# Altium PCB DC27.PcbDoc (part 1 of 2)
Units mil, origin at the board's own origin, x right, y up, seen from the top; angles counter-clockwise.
Board outline 2165.35 x 2165.35 mil, 4 copper layers (Top, Mid-Layer 1, Mid-Layer 2, Bottom), stack 65.59 mil thick; 50 components, 49 nets, 297 pads, 156 vias.
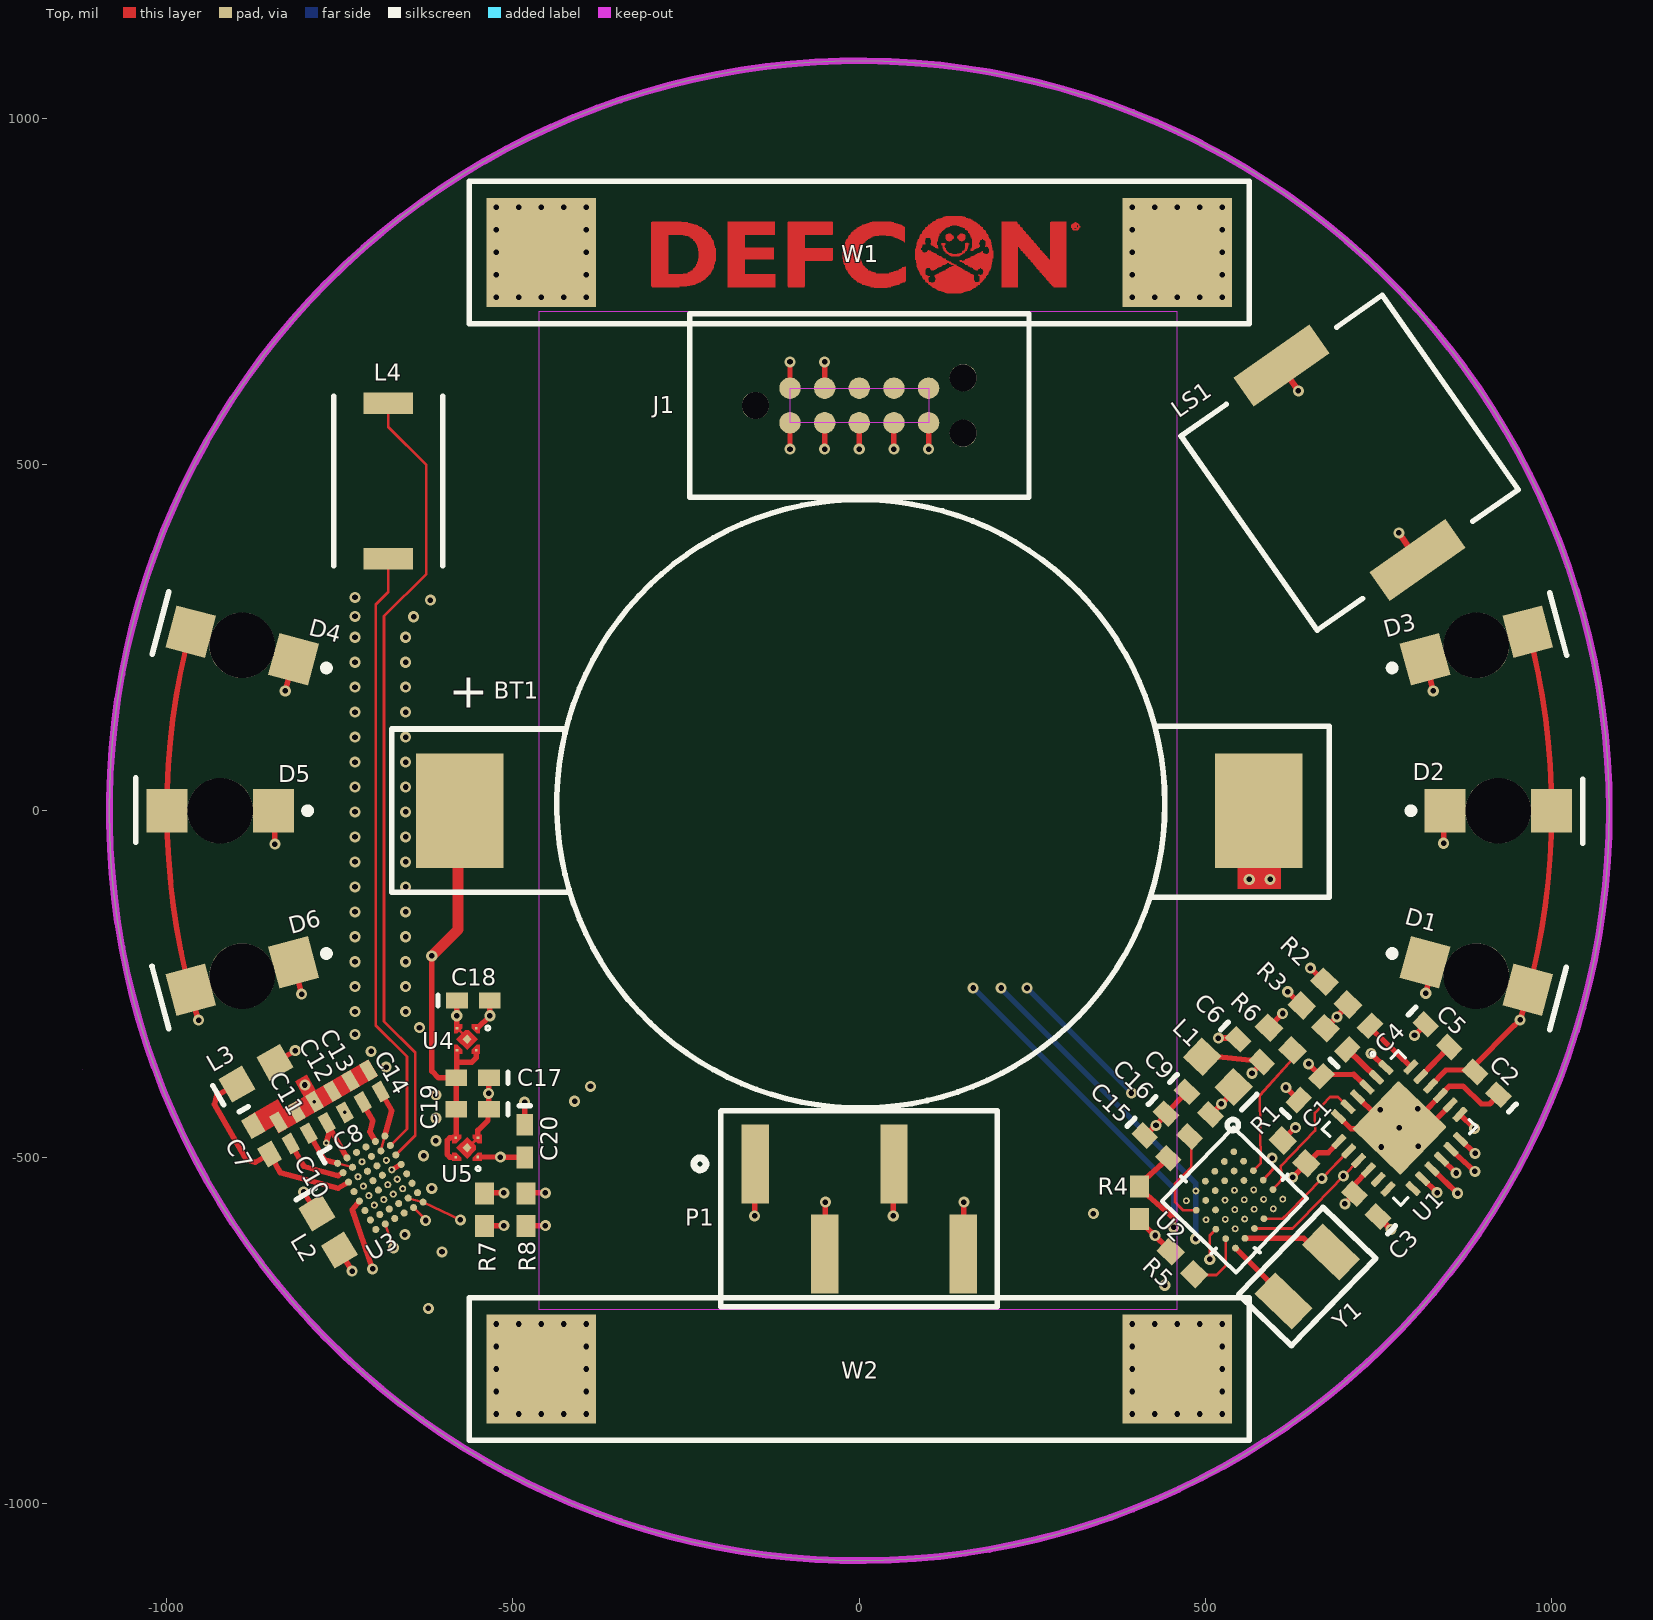
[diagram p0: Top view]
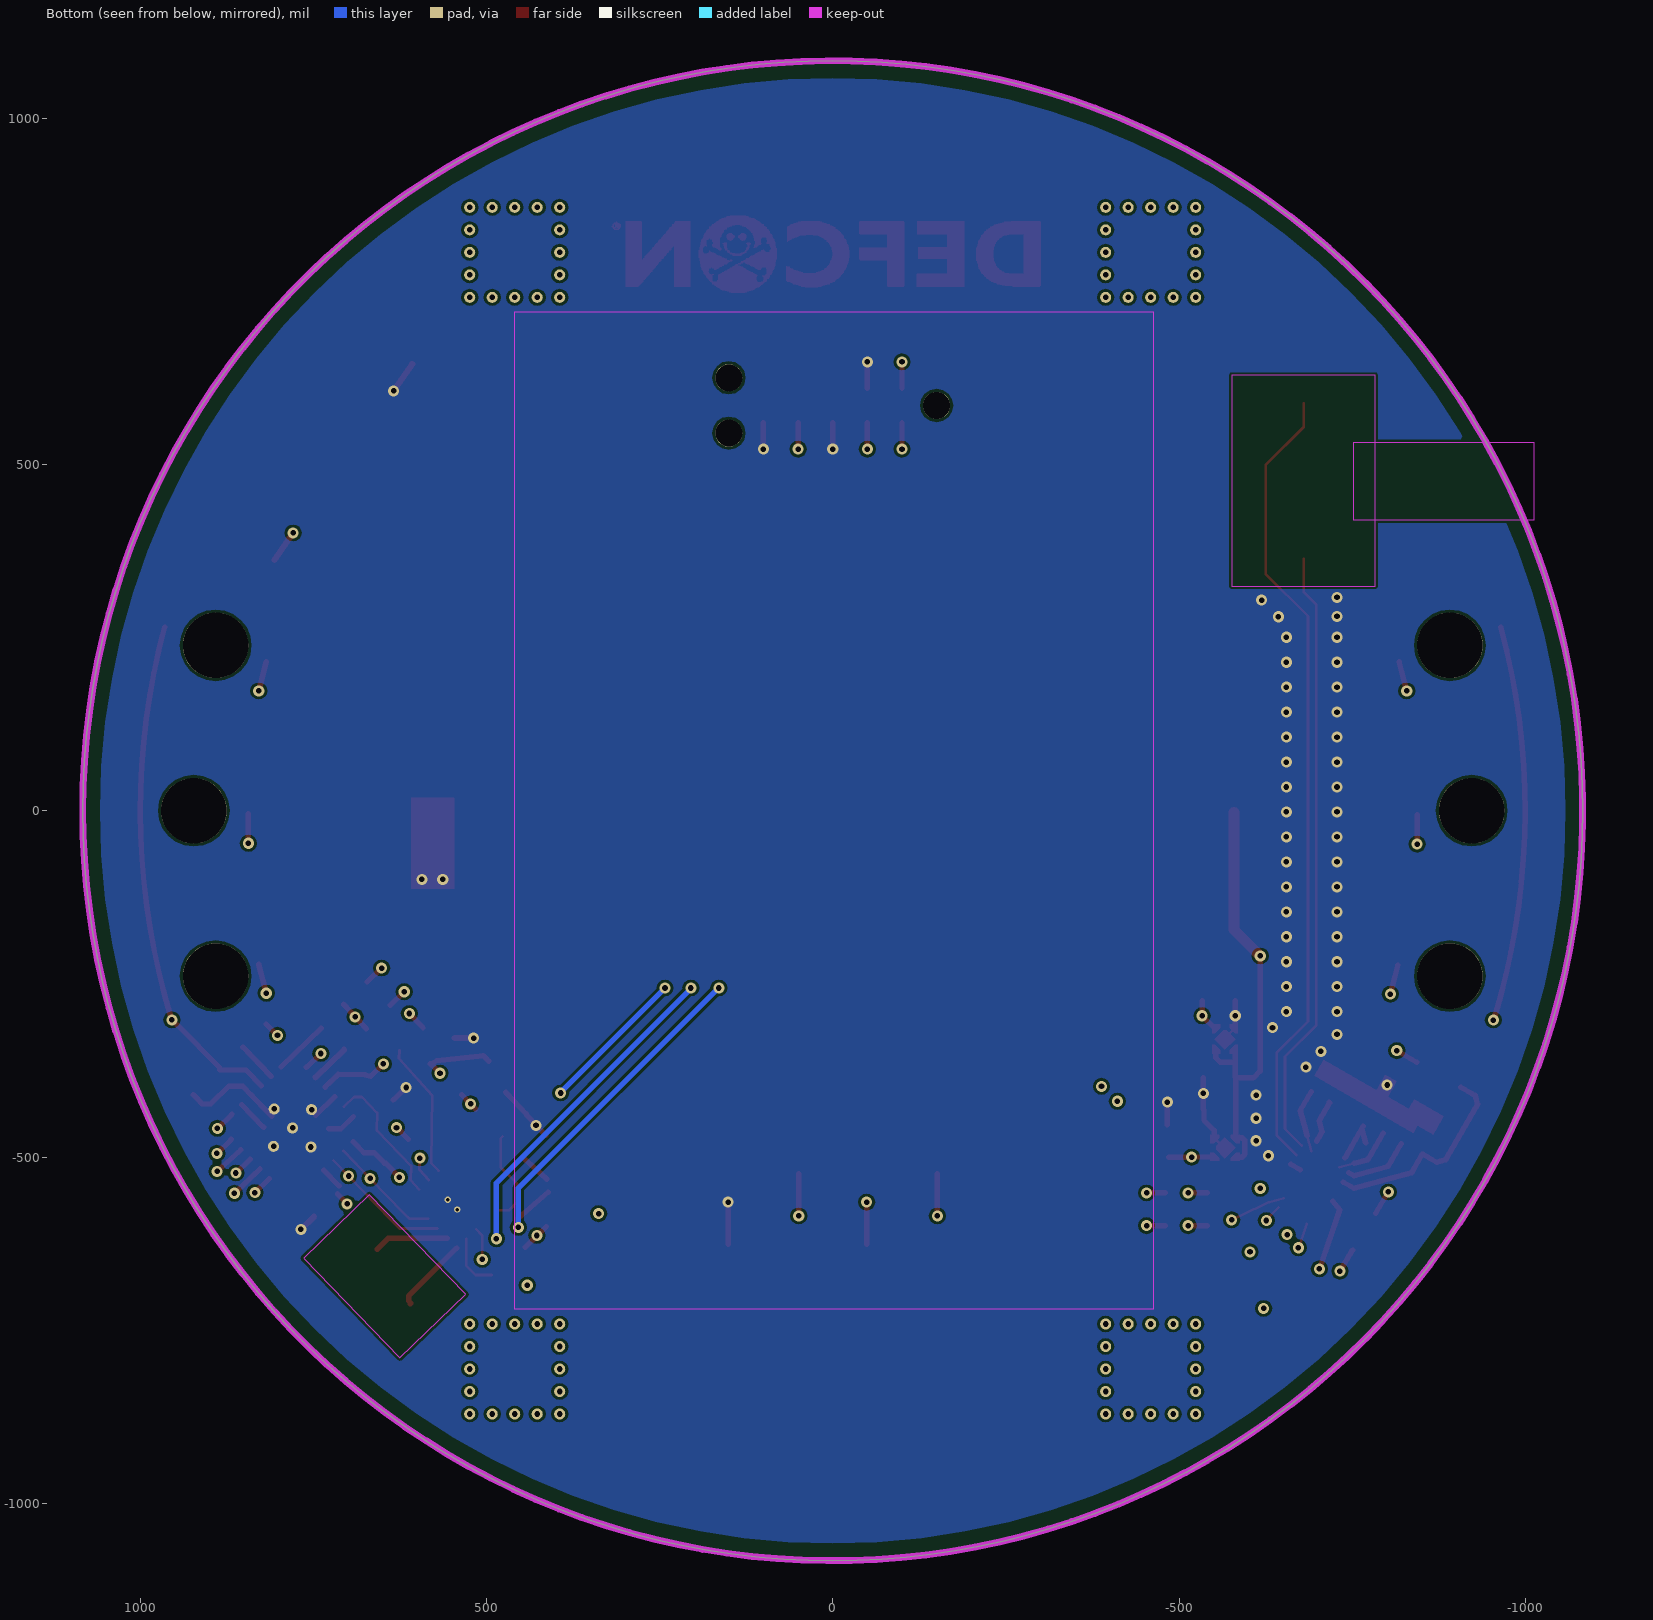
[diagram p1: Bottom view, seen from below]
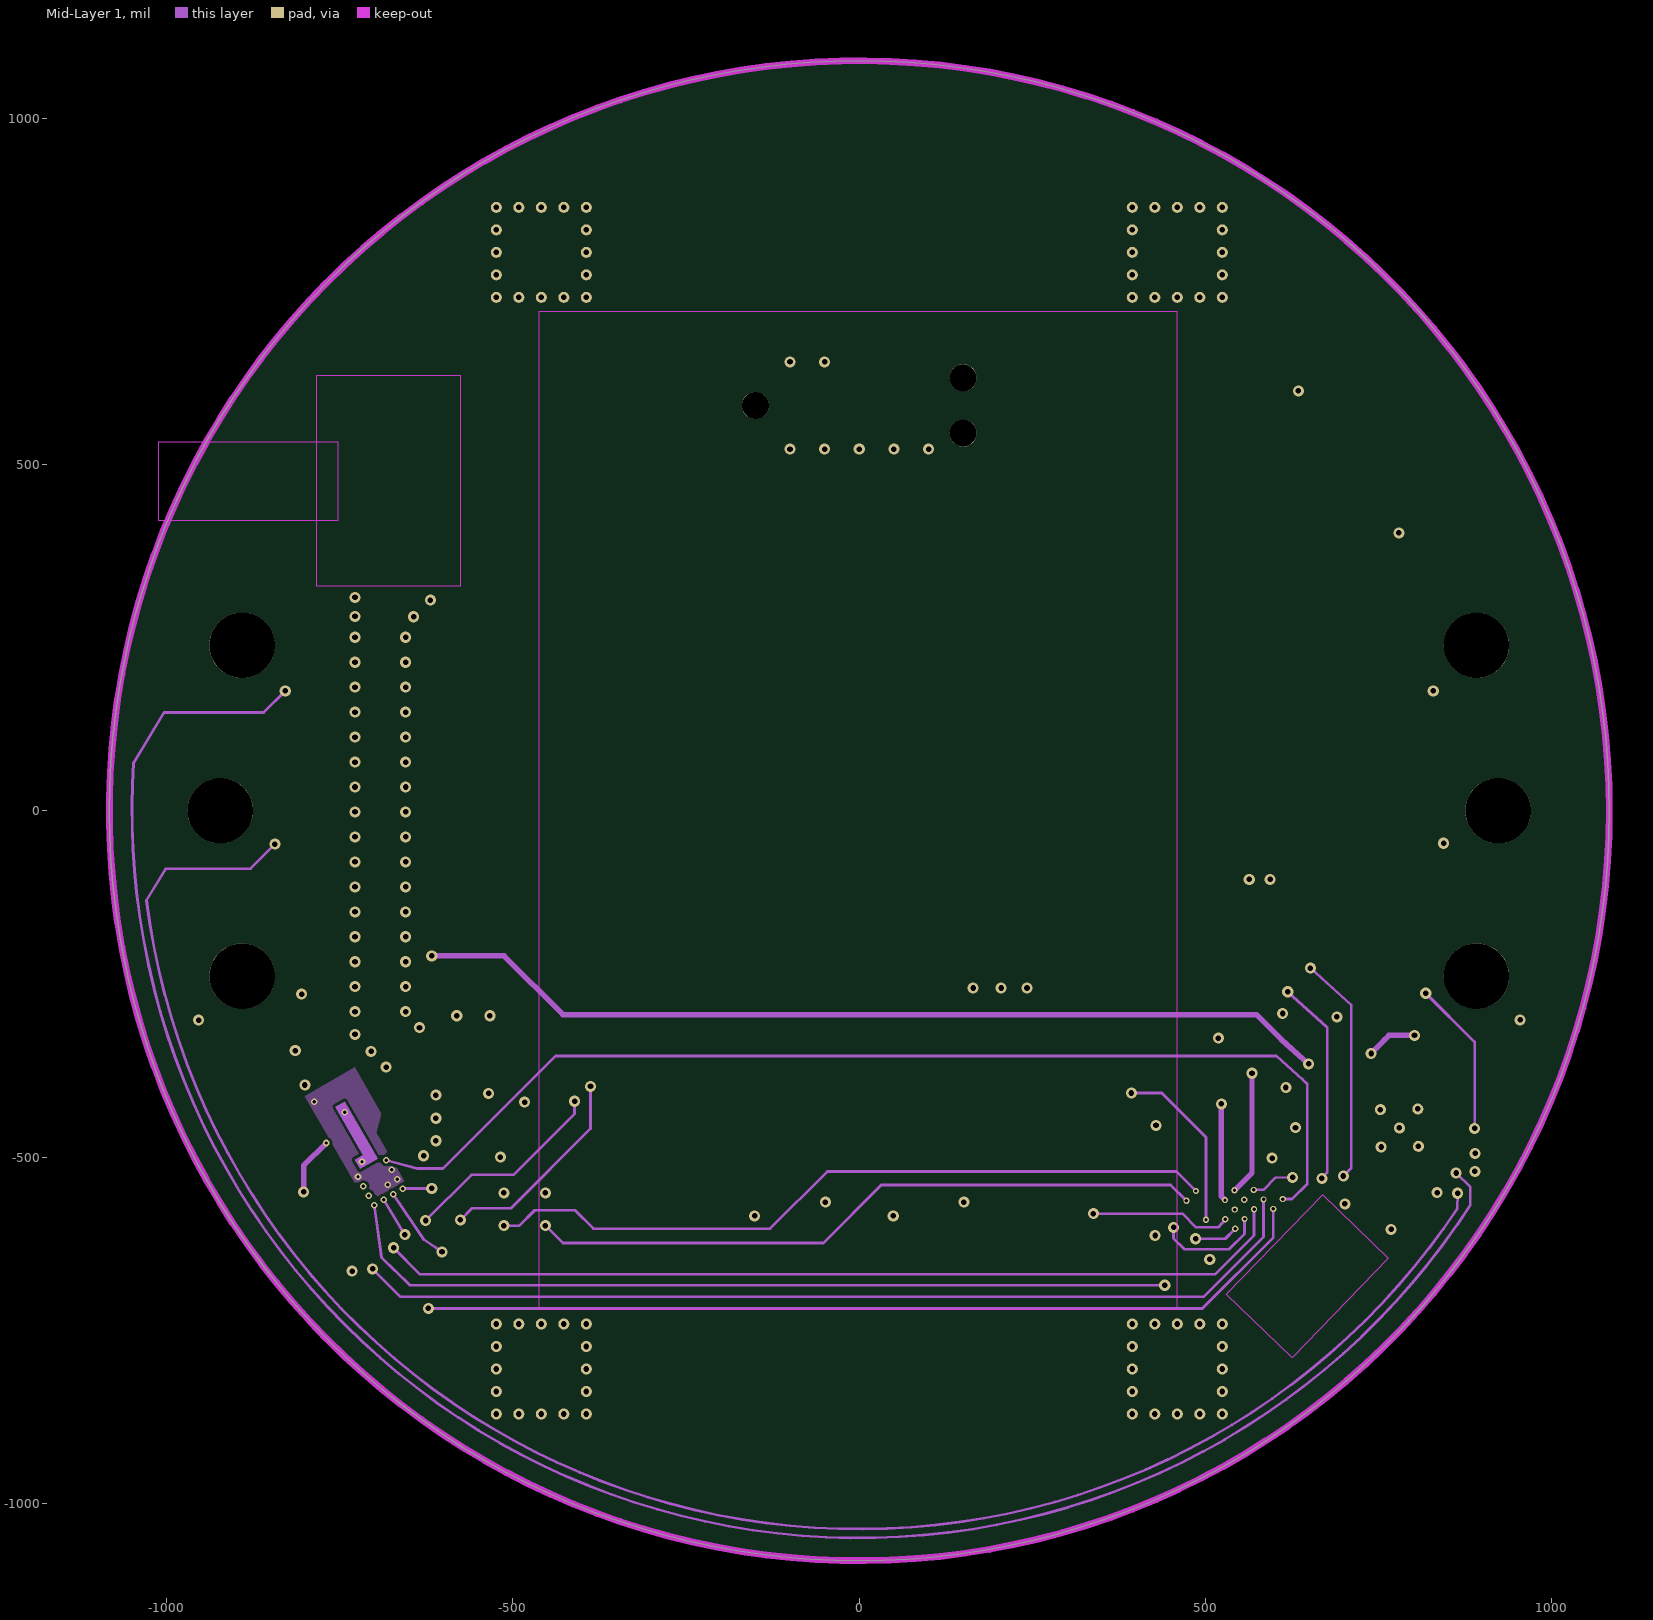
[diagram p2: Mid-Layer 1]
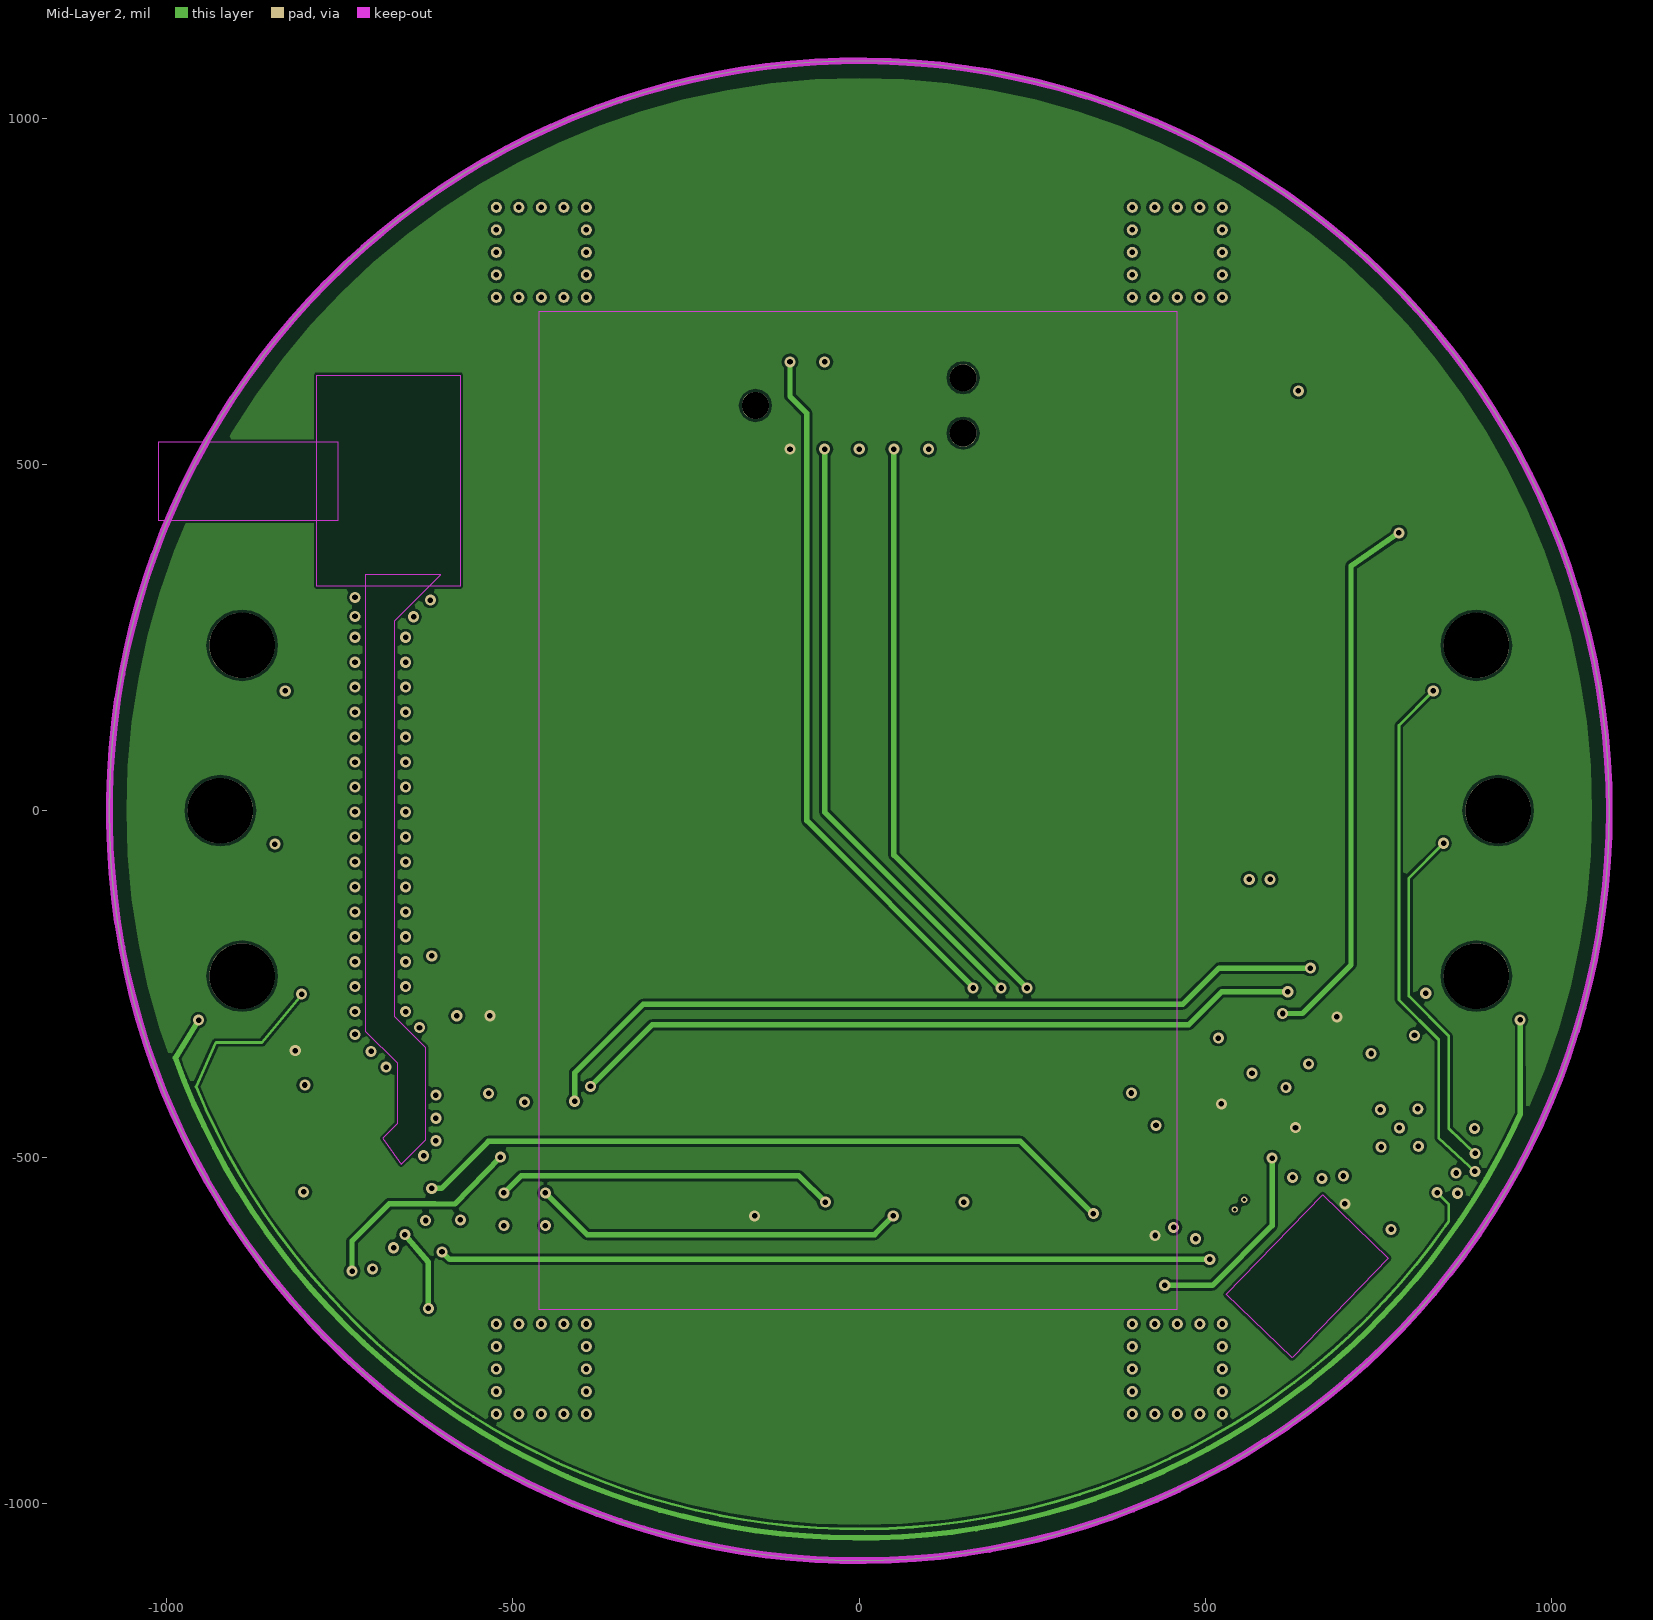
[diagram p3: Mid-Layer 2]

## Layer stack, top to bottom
Top Solder: solder mask 0.4, Solder Resist, Dk 3.5
Top: signal copper 1.2992
Dielectric1: core 2.5591, FR-4, Dk 4.8
Mid-Layer 1: signal copper 1.3779
Dielectric3: dielectric 55.1181, FR-4, Dk 4.8
Mid-Layer 2: signal copper 1.3779
Dielectric2: dielectric 2.5591, FR-4, Dk 4.8
Bottom: signal copper 1.2992
Bottom Solder: solder mask 0.4, Solder Resist, Dk 3.5

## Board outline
0,-1082.68 cw(c0,0) -1082.68,0 cw(c0,0) 0,1082.68 cw(c0,0) 1082.68,0 cw(c0,0)

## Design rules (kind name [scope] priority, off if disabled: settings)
Clearance Clearance_InnerLogo [All vs (OnLayer('Mid-Layer 1') AND InNamedUnion('DC27 Inner'))] p1: gap=0 ignorepadtopadclearanceinfootprint=FALSE
Clearance Clearance_Logos [(InNamedUnion('Pin 1 Logo')) OR (InNamedUnion('Logos'))] p2: gap=-19.68 ignorepadtopadclearanceinfootprint=FALSE
Clearance Clearance_Keepout [OnLayer('Keep-Out Layer')] p3: gap=20 ignorepadtopadclearanceinfootprint=FALSE
Clearance [All] p4: gap=3.94 ignorepadtopadclearanceinfootprint=FALSE
ComponentClearance [All] p1 off: gap=0 collisioncheckmode=3 verticalgap=10 showdistances=FALSE
FabricationTestPointUsage TestPointUsage [All] p1: valid=0 allowmultiple=FALSE
FabricationTestpoint Testpoint [All] p1: side=3 testpointundercomponent=TRUE minsize=40 maxsize=100 preferedsize=60 minholesize=0 maxholesize=40 preferedholesize=32 testpointgrid=1 allowsidetop=TRUE allowsidebottom=TRUE usegrid=TRUE gridtolerance=0.01
HoleSize [All] p1: absolutevalues=TRUE maxlimit=250 minlimit=4.92 maxpercent=80.000 minpercent=20.000
MinimumAnnularRing MinimumAnnularRing_1 [(IsVia)] p1: minimumring=2.01
MinimumAnnularRing [All] p2: minimumring=3.98
PolygonConnect PolygonConnect_1 [All] p1: connectstyle=Direct reliefconductorwidth=35 reliefentries=4 polygonreliefangle="90 Angle" airgapwidth=10
RoutingVias [All] p1: holewidth=16 width=26 viastyle="Through Hole" minholewidth=10 minwidth=20 maxholewidth=16 maxwidth=26
ShortCircuit ShortCircuit_Logo [InNet('GND') vs (OnLayer('Mid-Layer 1') AND InNamedUnion('DC27 Inner'))] p1: allowed=TRUE
ShortCircuit [All] p2: allowed=FALSE
SilkToSolderMaskClearance SilkscreenOverComponentPads [IsPad] p1: minsilkscreentomaskgap=10 clearancetoexposedcopper=TRUE
SolderMaskExpansion SolderMaskExpansion_1 [(IsVia)] p1: expansion=-15 istentingtop=FALSE
SolderMaskExpansion [All] p2: expansion=4 istentingtop=FALSE
UnRoutedNet [All] p1: checkbadconnections=TRUE
Width Width_Logos [(InNamedUnion('Pin 1 Logo')) OR (InNamedUnion('Logos'))] p1: maxlimit=10 minlimit=0.04 preferedwidth=0.04
Width Width_InnerLogo [(OnLayer('Mid-Layer 1') AND InNamedUnion('DC27 Inner'))] p2: maxlimit=10 minlimit=0.04 preferedwidth=0.83 checkconnectedcopper=TRUE
Width [All] p3: maxlimit=20 minlimit=3.94 preferedwidth=3.94
23 further rules are at their usual default settings.

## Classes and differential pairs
net class NFMI: NetL4_1 NetL4_2

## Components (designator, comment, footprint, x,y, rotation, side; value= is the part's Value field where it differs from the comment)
BT1 "BU2032SM-JJ-GTR" BU2032SM 0,0 r0 top locked
C1 "Cap" CAPC1005N 650.75,-400.38 r46 top value=1uF
C2 "Cap" CAPC1005N 905.98,-393.55 r136 top value=1uF
C3 "Cap" CAPC1005N 731.71,-569.38 r136 top value=0.1uF
C4 "Cap" CAPC1005N 720.95,-327.47 r46 top value=1uF
C5 "Cap" CAPC1005N 834.76,-324.78 r316 top value=1uF
C6 "Cap" CAPC1005N 563.98,-346.46 r316 top value=0.1uF
C7 "Cap" CAPC1005N -863.06,-475.26 r300 top value=0.1uF
C8 "Cap" RESC0603N -777.65,-435.19 r120 top value=0.47uF
C9 "Cap" CAPC1005N 490.16,-422.24 r316 top value=0.1uF
C10 "Cap" RESC0603N -829.61,-465.19 r120 top value=0.47uF
C11 "Cap" RESC0603N -803.63,-450.19 r120 top value=0.47uF
C12 "Cap" RESC0603N -751.67,-420.19 r120 top value=0.47uF
C13 "Cap" RESC0603N -725.69,-405.19 r120 top value=0.47uF
C14 "Cap" RESC0603N -699.71,-390.19 r120 top value=0.47uF
C15 "Cap" CAPC1005N 429.13,-485.24 r316 top value=0.1uF
C16 "Cap" CAPC1005N 459.65,-453.74 r316 top value=0.1uF
C17 "Cap" CAPC1005N -558.26,-385.7 r180 top value=1uF
C18 "Cap" CAPC1005N -557,-274 r0 top locked value=1uF
C19 "Cap" CAPC1005N -558.26,-430.7 r180 top value=1uF
C20 "Cap" CAPC1005N -483,-477 r270 top value=1uF
D1 "LED" APTR3216 792.06,-212.23 r345 top locked
D2 "LED" APTR3216 820,0 r0 top locked
D3 "LED" APTR3216 792.06,212.23 r15 top locked
D4 "LED" APTR3216 -792.06,212.23 r165 top locked
D5 "LED" APTR3216 -820,0 r180 top locked
D6 "LED" APTR3216 -792.06,-212.23 r195 top locked
J1 "DNP" TC2050-IDC-NL-FP 0,585 r0 top locked
L1 "Inductor" INDC1608N 517.72,-376.97 r136 top value=1000R@100MHz
L2 "Inductor" INDC1608N -766.73,-607.28 r301 top value=1000R@100MHz
L3 "Inductor" INDC1608N -871,-379 r30 top value=1000R@100MHz
L4 "Inductor" INDC6040 -680,476 r270 top value=MTNF6040FS3R7JTFY01
LS1 "PKMCS0909E4000-R1" PKMCS0909E4000 806,362 r125 top locked
P1 "DNP" "HEADER4 - SMD" 0,-575 r0 top locked
R1 "Res1" RESC1005N 628.35,-492.45 r136 top value=10k
R2 "Res1" RESC1005N 688.63,-263.23 r316 top value=10k
R3 "Res1" RESC1005N 655.93,-297.47 r316 top value=10k
R4 "Res1" RESC1005N 404.53,-565.94 r270 top value=10k
R5 "Res1" RESC1005N 466.54,-652.56 r136 top value=10k
R6 "Res1" RESC1005N 608.47,-329.52 r316 top value=1k
R7 "Res1" RESC1005N -541,-576 r90 top value=1k
R8 "Res1" RESC1005N -481,-576 r90 top value=1k
U1 "LP5569RTWR" VQFN50P400X400X100-24N 779.8,-457.98 r316 top
U2 "MKL27Z64VDA4" SOT1558-1 541.87,-561.86 r316 top value=Value
U3 "NXH2261UK" SOT1887_NXP -695.33,-530.17 r30 top
U4 "LD39020DTPU18R" VREG_LD39020DTPU33R -566.26,-329.7 r90 top
U5 "LD39020DTPU13R" VREG_LD39020DTPU33R -566.27,-486.7 r0 top
W1 "MJW-0.8" MJW-0.8-WITH-VIAS 0,806 r0 top locked
W2 "MJW-0.8" MJW-0.8-WITH-VIAS 0,-806 r0 top locked
Y1 "XTL_HC49-4H" ABS07 612.39,-707.79 r46 top value=32.768kHz

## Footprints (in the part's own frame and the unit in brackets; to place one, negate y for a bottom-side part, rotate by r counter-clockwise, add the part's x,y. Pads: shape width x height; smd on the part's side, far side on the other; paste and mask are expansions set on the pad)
ABS07 [mm] "Abracon ABS07 Crystal Oscillator"
  rect 1.1x1.9 smd: 1(0,0) 2(2.5,0)
  silkscreen extent -0.97,-1.35 3.47,1.35
APTR3216 [mm] "Kingbright 3.2 x 1.6 mm Surface Mount Chip LED Lamp"
  round 2.4 hole 2.4 unplated: 0(2.6,0)
  rect 1.5x1.6 smd: 1(4.554,0) 2(0.646,0)
  silkscreen extent -0.71,-1.2 5.7,1.16
BU2032SM [mm] "MPD 2032 SMT holder"
  rect 3.2x4.2 smd: 1(-14.65,0) 2(14.65,0)
  silkscreen extent -17.14,-10.9 17.23,11.4
CAPC1005N [mm] "Chip Capacitor, Body 1.0x0.5mm, IPC Medium Density"
  rect 0.8x0.6 smd: 1(-0.6,0) 2(0.6,0)
  silkscreen extent -1.3,-0.2 -1.3,0.2, body extent -0.55,-0.3 0.55,0.3, height 0.6
"HEADER4 - SMD" [mm] "Harwin M20-8770442"
  rect 1x2.9 smd paste-1.905: 1(-3.81,1.655) 2(-1.27,-1.655) 3(1.27,1.655) 4(3.81,-1.655)
  silkscreen extent -6.06,-3.59 5.05,3.6
INDC1608N [mm] "Chip Inductor, Body 1.6x0.8mm, IPC Medium Density"
  rect 1x1 smd: 1(-0.8,0) 2(0.8,0)
  silkscreen extent -1.6,-0.4 -1.6,0.4, body extent -0.88,-0.48 0.87,0.48, height 0.71
INDC6040 [mm] "Sunlord MTNF Series NFMI Antenna, Body 6.2x4.0mm"
  rect 0.8x1.8 smd: 1(-2.85,0) 2(2.85,0)
  silkscreen extent -3.1,-2 3.1,2
MJW-0.8-WITH-VIAS [mil] "Mac 8 MJW High Current Jumper w/ Stitching Vias for Support"
  round 16 hole 8 mask+4: 0(-524,-64.92) 0(-524,-32.44) 0(-524,0.04) 0(-524,32.52) 0(-524,65) 0(-491.52,-64.92) 0(-491.52,65) 0(-459.04,-64.92) 0(-459.04,65) 0(-426.56,-64.92) 0(-426.56,65) 0(-394.08,-64.92) 0(-394.08,-32.44) 0(-394.08,0.04) 0(-394.08,32.52) 0(-394.08,65) 0(394.11,-64.92) 0(394.11,-32.44) 0(394.11,0.04) 0(394.11,32.52) 0(394.11,65) 0(426.59,-64.92) 0(426.59,65) 0(459.07,-64.92) 0(459.07,65) 0(491.55,-64.92) 0(491.55,65) 0(524.03,-64.92) 0(524.03,-32.44) 0(524.03,0.04) 0(524.03,32.52) 0(524.03,65)
  rect 157.48x157.48 smd: 0(-459.06,0) 0(459.06,0)
  silkscreen extent -563,-103 563,103
PKMCS0909E4000 [mm] "Murata Piezo Element, 9mm x 9mm, 4kHz Fo, 65dB SPL min."
  rect 1.3x3.4 smd: 1(0,0) 2(8.7,0)
  silkscreen extent 0,-4.5 8.7,4.5
RESC0603N [mm] "Chip Resistor, Body 0.6x0.3mm, IPC Medium Density"
  rect 0.7x0.4 smd: 1(-0.45,0) 2(0.45,0)
  body extent -0.32,-0.17 0.32,0.16, height 0.3
RESC1005N [mm] "Chip Resistor, Body 1.1x0.5mm, IPC Medium Density"
  rect 0.8x0.7 smd: 1(-0.6,0) 2(0.6,0)
  body extent -0.55,-0.3 0.55,0.3, height 0.4
SOT1558-1 [mm] "NXP 98ASA00708D, XFBGA-36, 3.5x3.5mm, 0.5mm P"
  round 0.25 smd paste+0.01 mask+0.055: A1(-1.25,1.25) A2(-0.75,1.25) A3(-0.25,1.25) A4(0.25,1.25) A5(0.75,1.25) A6(1.25,1.25) B1(-1.25,0.75) B2(-0.75,0.75) B3(-0.25,0.75) B4(0.25,0.75) B5(0.75,0.75) B6(1.25,0.75) C1(-1.25,0.25) C2(-0.75,0.25) C3(-0.25,0.25) C4(0.25,0.25) C5(0.75,0.25) C6(1.25,0.25) D1(-1.25,-0.25) D2(-0.75,-0.25) D3(-0.25,-0.25) D4(0.25,-0.25) D5(0.75,-0.25) D6(1.25,-0.25) E1(-1.25,-0.75) E2(-0.75,-0.75) E3(-0.25,-0.75) E4(0.25,-0.75) E5(0.75,-0.75) E6(1.25,-0.75) F1(-1.25,-1.25) F2(-0.75,-1.25) F3(-0.25,-1.25) F4(0.25,-1.25) F5(0.75,-1.25) F6(1.25,-1.25)
  silkscreen extent -2.16,-2.01 2.01,2.13
SOT1887_NXP [mm] "SOT1887_NXP"
  round 0.26 smd paste+0.008 mask+0.04: A1(-1,1.2) A2(-0.6,1.2) A3(-0.2,1.2) A4(0.2,1.2) A5(0.6,1.2) A6(1,1.2) B1(-1,0.8) B2(-0.6,0.8) B3(-0.2,0.8) B4(0.2,0.8) B5(0.6,0.8) B6(1,0.8) C1(-1,0.4) C2(-0.6,0.4) C3(-0.2,0.4) C4(0.2,0.4) C5(0.6,0.4) C6(1,0.4) D1(-1,0) D2(-0.6,0) D3(-0.2,0) D4(0.2,0) D5(0.6,0) D6(1,0) E1(-1,-0.4) E2(-0.6,-0.4) E3(-0.2,-0.4) E4(0.2,-0.4) E5(0.6,-0.4) E6(1,-0.4) F1(-1,-0.8) F2(-0.6,-0.8) F3(-0.2,-0.8) F4(0.2,-0.8) F5(0.6,-0.8) F6(1,-0.8) G1(-1,-1.2) G2(-0.6,-1.2) G3(-0.2,-1.2) G4(0.2,-1.2) G5(0.6,-1.2) G6(1,-1.2) H1(-1,-1.6) H2(-0.6,-1.6) H3(-0.2,-1.6) H4(0.2,-1.6) H5(0.6,-1.6) H6(1,-1.6)
  silkscreen extent -1.4,1.45 -0.95,1.85
TC2050-IDC-NL-FP [mil] "Tag-Connect TC2050-IDC-NL Plug-of-Nails Cable"
  round 39 hole 39 unplated paste-393.7: 0(-150,0) 0(150,-40) 0(150,40)
  round 31 smd paste-30: 1(-100,-25) 2(-50,-25) 3(0,-25) 4(50,-25) 5(100,-25) 6(100,25) 7(50,25) 8(0,25) 9(-50,25) 10(-100,25)
  Top keep-out region: -100,25 100,25 100,-25 -100,-25
  silkscreen extent -245,-133 245,133
VQFN50P400X400X100-24N [mm]
  rrect42% 0.6x0.24 smd mask+0.06: 1(-1.9,1.25) 2(-1.9,0.75) 3(-1.9,0.25) 4(-1.9,-0.25) 5(-1.9,-0.75) 6(-1.9,-1.25) 13(1.9,-1.25) 14(1.9,-0.75) 15(1.9,-0.25) 16(1.9,0.25) 17(1.9,0.75) 18(1.9,1.25)
  rrect42% 0.24x0.6 smd mask+0.06: 7(-1.25,-1.9) 8(-0.75,-1.9) 9(-0.25,-1.9) 10(0.25,-1.9) 11(0.75,-1.9) 12(1.25,-1.9) 19(1.25,1.9) 20(0.75,1.9) 21(0.25,1.9) 22(-0.25,1.9) 23(-0.75,1.9) 24(-1.25,1.9)
  round 0.406 hole 0.203 mask+0.102: 25(-0.97,0) 25(0,-0.97) 25(0,0.97) 25(0,0) 25(0.97,0)
  rrect3% 2.45x2.45 smd paste-7.62 mask+0.06: 25(0,0)
  silkscreen extent -2.66,-2 2,2
VREG_LD39020DTPU33R [mm]
  rect 0.1x0.1 smd paste-300 mask-300: 1(0.395,-0.335) 2(0.4,0.37) 3(-0.41,0.37) 4(-0.41,-0.34)
  rect 0.25x0.25 smd rot 45 mask-300: 5(0,0)
  Top region: -0.39,-0.175 -0.54,-0.175 -0.54,-0.475 -0.21,-0.475 -0.21,-0.355
  Top region: 0.39,0.175 0.54,0.175 0.54,0.475 0.21,0.475 0.21,0.355
  Top region: 0.39,-0.175 0.54,-0.175 0.54,-0.475 0.21,-0.475 0.21,-0.355
  Top region: -0.39,0.175 -0.54,0.175 -0.54,0.475 -0.21,0.475 -0.21,0.355
  Top region: -0.39,0
  Top region: -0.396,0 0,0.395 0.326,0.069 0.326,-0.069 0,-0.396
  silkscreen extent 0.33,-0.84 0.48,-0.69

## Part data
BT1: library part Battery, "Single Cell Battery Holder"
C1 C2 C4 C5 C17 C18 C19 C20: "CL05A105KP5NNNC"
C3 C6 C7 C9 C15 C16: "C0402C104K8PAC"
C8 C10 C11 C12 C13 C14: "Taiyo Yuden AMK063BJ474MP-F"
D1 D2 D3 D4 D5 D6: "Kingbright APTR"
J1: library part ARM_SWD_10, "TC2050-IDC-NL-050-ALL"
L1 L2 L3: "BLM18RK102SN1D"
LS1: library part Speaker, "Loudspeaker"
P1: library part "Header 4", "Header, 4-Pin"
R1 R2 R3 R4 R5 R6 R7 R8: "Resistor"
U1: library part LP5569, "TI I2C 9-channel LED Driver"
U2: Manufacturer_Part_Number=mkl27z64vda4
U3: library part NXH2261, "NXP NFMI"
U4 U5: library part LD30920, "ST Low-Dropout Linear Regulator (DFN1x1-4L)"
W1 W2: library part Jumper, "Jumper Wire"
Y1: "Abracon ABS07-32.768KHZ-1-T", Manufacturer #1=Citizen, Manuf Part No=HC49US30.000MAJB, Part Number="Digikey HC49US30.000MAJB-ND"

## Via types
v1: diameter 16, hole 8, Top to Bottom, 126 vias
v2: diameter 9.45, hole 4.92, Top to Mid-Layer 1, 15 vias
v3: diameter 9.06, hole 4.92, Top to Mid-Layer 1, 13 vias
v4: diameter 9.06, hole 4.92, Top to Bottom, 2 vias

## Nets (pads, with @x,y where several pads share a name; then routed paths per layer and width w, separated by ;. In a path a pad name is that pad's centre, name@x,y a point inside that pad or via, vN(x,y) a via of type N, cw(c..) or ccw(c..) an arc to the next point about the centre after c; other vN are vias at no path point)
1V3: C20.2 L2.2 U5.1 | length 409.8
  Top w7.87: L2.2@-750.51,-634.28 v1(-732.23,-664.71) ; U5.1@-550.72,-499.89 v1@-517.99,-499.89 ; v1@-517.99,-500.28 C20.2@-485.27,-500.28
  Mid-Layer 2 w7.87: v1@-732.28,-664.71 -732.28,-621.06 -678.41,-567.19 -612.93,-567.19 -583.62,-567.73 v1(-517.99,-500.09)
1V8: C3.2 C9.2 C18.2 J1.1 L1.1 L3.2 P1.1 R1.2 R2.2 R3.2 R4.2 R5.2 U1.10 U2.D3 U4.1 | length 522.2
  Top w7.87: L3.2@-843,-363 v1(-814.28,-346.42) ; U4.1@-553.07,-314.15 -551.54,-314.15 v1(-533.38,-295.98) C18.2@-533.38,-274 ; v1(-151,-585) P1.1@-151,-524 ; v1(-100,522) J1.1@-100,560 ; R4.2@413.27,-600.25 426.81,-613.55 R5.2@443.92,-630.36 ; C9.2@515.52,-430.73 v1(522.8,-423.23) L1.1@535.69,-409.84 ; R1.2@612.65,-474.43 629.31,-457.17 v1@631.28,-455.14 ; R3.2@673.32,-314.46 673.43,-314.35 689.29,-297.44 705.82,-279.82 R2.2@706.27,-279.35 ; v1(700.96,-567.57) 700.47,-567.57 C3.2@714.89,-553.14 ; C3.2@712.72,-541.62 U1.10@734.92,-518.63
  Mid-Layer 1 w7.87: v1(522.8,-423.23) 522.8,-556.9 v3(527.95,-562.1)
  other v1: 427.17,-613.19 629.72,-457.56 689.46,-297.59
GND: BT1.2 C1.1 C2.1 C3.1 C6.1 C7.1 C8.2 C9.1 C10.2 C11.2 C12.2 C13.2 C14.2 C15.1 C16.1 C17.1 C18.1 C19.1 C20.1 J1.3 J1.5 J1.9 LS1.2 P1.4 U1.4 U1.6 U1.20 U1.21 U1.25 U2.C4 U2.D4 U3.C2 U3.D5 U3.D6 U3.E4 U3.E5 U4.2 U4.5 U5.2 U5.5 | length 881.4
  Top w3.94: U4.2@-580.83,-313.95 U4.5@-566.26,-328.52 ; C18.1@-580.83,-274.2 C18.1@-580.62,-274 ; U5.5@-565.09,-486.7 U5.2@-550.52,-472.13 ; C19.1@-536,-432.06 C19.1@-534.64,-430.7
  Top w7.87: v2(-674.87,-518.36) U3.D6@-661.24,-510.49 ; U4.2@-580.83,-313.95 C18.1@-580.83,-274.2 ; U5.2@-550.52,-472.13 -550.52,-461.52 -536,-447 C19.1@-536,-432.06 ; C19.1@-534.64,-430.7 C17.1@-534.64,-385.7 ; C20.1@-483,-453.38 v1(-483,-420.65) ; J1.9@-50,610 v1(-50,648) ; v1(0,522) J1.3@0,560 ; v1(100,522) J1.5@100,560 ; P1.4@151,-626 v1(151,-565) ; C15.1@414.15,-468.74 428.06,-454.05 C16.1@441.95,-439.4 ; C16.1@442.75,-437.42 C9.1@472.02,-406.53 ; v1(615.84,-399.58) C1.1@634.34,-417.38 ; U1.6@691.81,-441.42 710.22,-459.2 U1.25@727.49,-458.9 ; U1.4@719.16,-413.1 745.5,-438.54 U1.25@746.35,-439.36 ; U1.25@809.81,-441.08 813.41,-437.35 U1.21@838.85,-411.01 851.38,-398.04 871.4,-397.69 898.01,-423.39 910.2,-423.18 C2.1@922.97,-409.96 ; U1.25@821.56,-457.26 U1.20@853.01,-424.69
  Top w9: v1(518.33,-328.17) C6.1@545.85,-328.17 ; LS1.2@607,645 608.96,642.17 v1(634,606) ; C3.1@748.7,-585.79 767.24,-604.33 v1(767.72,-604.33)
  other v1: -628.94,-498.03 -611.22,-476.38 428.37,-454.35 -611.22,-443.9 -611.22,-410.43 -535,-408 -800.3,-395.97 -683.07,-370.08 -704.72,-347.44 -728,-322.89 -634.84,-312.99 -581.03,-296 -728,-290.08 -655,-290.07 -728,-254.04 -655,-254.03 -728,-218.01 -655,-218 -728,-181.98 -655,-181.97 -728,-145.94 -655,-145.93 -728,-109.91 -655,-109.9 563,-99 593,-99 -728,-73.87 -655,-73.87 -728,-37.84 -655,-37.83 -728,-1.81 -655,-1.8 -728,34.23 -655,34.23 -728,70.26 -655,70.26 -728,106.3 -655,106.3 -728,142.33 -655,142.33 -728,178.36 -655,178.36 -728,214.4 -655,214.4 -728,250.43 -655,250.43 -643.38,280 -727.99,280.51 -619.09,304.13 -727.99,308.07
  other v2: -680.64,-539.87 -667,-532 -723.66,-528.35 -786.51,-419.84
  other v4: 542.11,-575.77 555.79,-561.61
KL_nRESET: C15.2 J1.10 R4.1 U2.D5 | length 1786.8
  Top w3.94: C15.2@446.13,-501.78 C15.2@446.13,-501.65
  Top w7.87: J1.10@-100,610 v1(-100,648) ; R4.1@410.68,-550.56 454.09,-588.38 v1@453.98,-601.38 ; R4.1@412.69,-532.09 C15.2@446.13,-501.65
  Mid-Layer 1 w3.94: v1(453.74,-601.38) 453.74,-617.26 469.53,-633.05 534.04,-633.05 556.27,-610.81 v3(556.27,-589.45)
  Mid-Layer 2 w7.87: v1(-100,648) -100,598 -75.79,573.79 -75.79,-14.21 v1@165.14,-255.14
  Bottom w7.87: v1@165.41,-256.41 453.74,-544.74 453.74,-599.41 v1(453.74,-601.38)
  other v1: 164.37,-255.91
KL_PIEZO: R6.2 U2.A3 | length 196.5
  Top w3.94: U2.A3@568.98,-519.62 579.73,-508.48 578.03,-410.89 626.07,-357.54 R6.2@625.46,-345.93
KL_RX: R8.1 U2.F1 | length 1007.1
  Top w7.87: R8.1@-480.39,-599.02 v1(-453,-599.02)
  Mid-Layer 1 w3.94: v1(-453,-599.02) -428,-624.02 -51.89,-624.02 31.77,-540.35 449.57,-540.35 v3(472.28,-563.07)
KL_SWCLK: J1.4 U2.F3 | length 1362.6
  Top w7.87: v1(50,522) J1.4@50,560
  Mid-Layer 1 w3.94: v1(392.72,-407.48) 436.68,-407.48 500.6,-471.41 v3(500.6,-590.42)
  Mid-Layer 2 w7.87: v1(50,522) 50,-64 v1@242.02,-256.02
  Bottom w7.87: v1@242.02,-256.02 v1@393.1,-407.1
  other v1: 242.13,-255.91
KL_SWDIO: J1.2 U2.E5 | length 1462.7
  Top w7.87: v1(-50,522) J1.2@-50,560
  Mid-Layer 1 w3.94: v1(485.46,-617.85) 528.35,-617.85 v3(542.6,-603.61)
  Mid-Layer 2 w7.87: v1(-50,522) -50,-2 v1@204.32,-256.32
  Bottom w7.87: v1@204.31,-256.31 485.46,-537.46 v1(485.46,-617.85)
  other v1: 204.72,-255.91
KL_TX: R7.1 U2.E1 | length 1092.4
  Top w7.87: R7.1@-540.39,-599.02 v1(-513,-599.02)
  Mid-Layer 1 w3.94: v1(-513,-599.02) -490.75,-599.02 -468.5,-576.77 -410.43,-576.77 -383.86,-603.35 -128.65,-603.35 -46.11,-520.81 457.86,-520.81 v3(485.96,-548.91)
LED_EN: U1.5 U2.A5 | length 198.8
  Top w3.94: U2.A5@597.3,-546.97 609.65,-533.25 608.59,-512.96 658.13,-461.8 657.68,-436.2 679.61,-413.41 690.94,-413.21 U1.5@705.48,-427.26
LED_nINT: R1.1 U1.7 U2.B4 | length 152.2
  Top w7.87: v1(625.63,-529.28) R1.1@645.35,-508.86 647.29,-508.83 661.62,-493.99 676.87,-493.73 U1.7@692.44,-477.61
  Mid-Layer 1 w3.94: v3(569.46,-547.45) 583.82,-547.2 600.72,-529.71 v1(625.63,-529.28)
NetC4_1: C4.1 U1.2 | length 57.2
  Top w9: C4.1@705.36,-345.05 U1.2@746.51,-384.78
NetC4_2: C4.2 U1.24 | length 81
  Top w7.87: C4.2@738.12,-313.74 U1.24@796.37,-369.99
NetC5_1: C5.1 U1.1 | length 125.5
  Top w7.87: v1(739.03,-350.49) 759.88,-370.63 U1.1@760.18,-370.62 ; v1@801.75,-324.39 C5.1@817.77,-308.37
  Mid-Layer 1 w7.87: v1(739.03,-350.49) 758.14,-330.71 764.46,-324.39 v1(801.55,-324.39)
NetC5_2: C5.2 U1.23 | length 59.3
  Top w7.87: U1.23@810.53,-383.66 851.54,-341.19 C5.2@851.75,-341.19
NetC6_2: C6.2 L1.2 U2.C3 | length 287.1
  Top w7.87: L1.2@496.3,-361.42 498.77,-359.17 504.23,-353.45 571.98,-360.76 578.34,-365.41 C6.2@578.39,-365.47 ; v1(566.93,-378.94) 566.99,-378.94 C6.2@580.97,-364.96 ; C6.2@579,-366.05 C6.2@579.35,-366.39
  Mid-Layer 1 w7.87: v3(541.63,-547.94) 566.93,-522.64 v1(566.93,-378.94)
NetC7_2: C7.2 L3.1 U3.C1 | length 301.4
  Top w7.87: -930.99,-424.05 -884.8,-504.06 -871.75,-507.55 C7.2@-851.25,-495.72 ; -930.93,-424.01 -927.43,-410.96 L3.1@-906.93,-399.13 ; C7.2@-851.18,-495.84 -835.68,-522.69 -752.48,-544.98 U3.C1@-737.3,-536.22
NetC8_1: C8.1 L2.1 U3.A2 | length 195
  Top w3.94: L2.1@-783.82,-580.79 -783.12,-580.97 L2.1@-782.44,-581.14
  Top w7.87: v1(-802.1,-550.37) L2.1@-783.82,-580.79 ; v2(-769.29,-479.68) C8.1@-763.73,-458.95 ; C8.1@-765.6,-455.71 C8.1@-763.73,-458.95 ; U3.A2@-739.41,-501.07 C8.1@-763.73,-458.95
  Mid-Layer 1 w7.87: v1(-802.1,-550.37) -802.1,-512.49 v2(-769.29,-479.68)
NetC10_1: C10.1 U3.B1 | length 97.5
  Top w7.87: C10.1@-820.76,-480.53 -801.66,-513.61 -752.46,-526.79 U3.B1@-745.17,-522.58
NetC11_1: C11.1 U3.A1 U3.B2 | length 86.7
  Top w3.94: U3.A1@-753.05,-508.94 U3.B2@-731.54,-514.71
  Top w7.87: C11.1@-794.78,-465.53 -772.76,-503.66 U3.A1@-753.05,-508.94
NetC12_1: C12.1 U3.B3
  other v2: -717.9,-506.83 -742.81,-435.53
NetC13_1: C13.1 U3.A5 | length 63.7
  Top w7.87: C13.1@-716.83,-420.53 -717.2,-421.9 -702.2,-447.88 -706.44,-463.69 U3.A5@-698.5,-477.45
NetC14_1: C14.1 U3.A6 U3.B5 | length 91.8
  Top w3.94: U3.B5@-690.62,-491.09 U3.A6@-684.86,-469.57
  Top w7.87: C14.1@-690.85,-405.53 -675.04,-432.92 U3.A6@-684.86,-469.57
NetC16_2: C16.2 U2.F2 | length 141.4
  Top w3.94: C16.2@476.64,-470.15 479.37,-472.88 479.37,-514.72 455.71,-538.39 455.71,-564.96 467.49,-576.74 U2.F2@486.44,-576.74
NetD1_2: D1.2 U1.19 | length 296.7
  Top w7.87: v1(817.74,-263.46) 828.61,-221.95 D1.2@828.74,-221.46 ; U1.19@867.47,-438.36 v1(888.32,-458.49)
  Mid-Layer 1 w3.94: v1(817.74,-263.46) 888.32,-334.03 v1(888.32,-458.49)
NetD2_2: D2.2 U1.18 | length 580.6
  Top w7.87: v1(843.62,-47) D2.2@843.62,-4.2 ; U1.18@868.1,-474.54 v1(888.95,-494.68)
  Mid-Layer 2 w3.94: v1(843.62,-47) 793.31,-97.32 793.31,-267.72 851.11,-325.52 851.11,-459.18 v1(888.95,-494.68)
NetD3_2: D3.2 U1.17 | length 850.5
  Top w7.87: D3.2@817.62,214.91 v1(828.62,172.91) ; U1.17@854.48,-489.7 v1(888.78,-520.67)
  Mid-Layer 2 w3.94: v1(828.62,172.91) 779,123.28 779,-273.09 836.5,-330.6 836.5,-472.6 v1(888.78,-520.67)
NetD4_2: D4.2 U1.16 | length 3165.7
  Top w7.87: v1(-828.62,172.91) D4.2@-817.62,214.91 ; U1.16@840.75,-502.86 v1(861.6,-523)
  Mid-Layer 1 w3.94: v1(-828.62,172.91) -859.8,141.73 -1003.7,141.73 -1047.59,69.15 ccw(c0,0) -1043.29,-117.29 ccw(c0,0) 881.96,-569.53 882.1,-543.5 v1(861.6,-523)
NetD5_2: D5.2 U1.15 | length 2861.1
  Top w7.87: v1(-843.62,-48.3) D5.2@-843.62,-5.5 ; U1.15@826.78,-517.03 v1(863.9,-552.28)
  Mid-Layer 1 w3.94: v1(-843.62,-48.3) -878.98,-83.66 -1000.99,-83.66 -1028.92,-129.43 ccw(c0,0) 863.33,-574.54 863.36,-574.51 v1(863.9,-552.28)
NetD6_2: D6.2 U1.14 | length 2565.6
  Top w7.87: D6.2@-815.93,-222.8 v1(-804.93,-264.8) ; U1.14@813.4,-531.18 v1(834.25,-551.32)
  Mid-Layer 2 w3.94: v1@-804.55,-265.18 -862.2,-334.65 -928.74,-334.65 -957.4,-398.51 ccw(c0,0) 846.35,-599.27 ccw(c0,0) 851.03,-592.61 851.11,-568.18 v1(834.25,-551.32)
NetL4_1: L4.1 U3.C6 | length 1163.4
  Top w3.94: L4.1@-680,588.2 -680,554 -625,499 -625,342 -686,281 -686,-304 -641,-349 -641,-468.74 U3.C6@-669.11,-496.85
NetL4_2: L4.2 U3.B6 | length 883
  Top w3.94: L4.2@-680,363.8 -680,316 -698,298 -698,-310 -653,-355 -653,-459.23 U3.B6@-676.98,-483.21
NetLS1_1: LS1.1 R6.1 | length 863.3
  Top w7.87: R6.1@591.47,-313.11 v1(611.19,-292.7)
  Top w9: v1(779,401) LS1.1@806,362
  Mid-Layer 2 w7.87: v1(611.19,-292.7) 639.59,-292.7 709.84,-222.44 709.84,353.33 v1(779,401)
NetP1_2: P1.2 R7.2 | length 578.4
  Top w7.87: R7.2@-540.39,-551.77 v1(-513,-551.77) ; P1.2@-49,-626 v1(-49,-565)
  Mid-Layer 2 w7.87: v1(-513,-551.77) -488.23,-527 -87,-527 v1(-49,-565)
NetP1_3: P1.3 R8.2 | length 626.5
  Top w7.87: R8.2@-480.39,-551.77 v1(-453,-551.77) ; v1(49.02,-585) P1.3@49,-524
  Mid-Layer 2 w7.87: v1(-453,-551.77) -392.77,-612 22.02,-612 v1(49.02,-585)
NetR5_1: R5.1 U2.F5 | length 81.6
  Top w3.94: R5.1@492.13,-670.28 515.68,-670.28 528.93,-657.04 U2.F5@528.93,-617.77
NetU2_E6: U2.E6 Y1.2 | length 107.5
  Top w7.87: U2.E6@556.76,-617.28 641.85,-617.28 Y1.2@657.69,-633.12
NetU2_F6: U2.F6 Y1.1 | length 106.1
  Top w7.87: U2.F6@543.09,-631.44 612.39,-700.74 Y1.1@612.39,-707.79 ; Y1.1@609.25,-711.27 Y1.1@610,-711.94
NXH_CAL: U2.B6 U3.F3 | length 1481.5
  Mid-Layer 1 w3.94: v2(-686.4,-561.39) v1(-656,-612) ; v1(-622.05,-718.5) 495.08,-718.5 597.78,-615.8 v3(597.78,-574.8)
  Mid-Layer 2 w7.87: v1(-656,-612) -622.05,-651.57 v1(-622.05,-718.5)
NXH_DETECT: U2.A4 U3.F2 | length 1548.8
  Top w3.94: U2.A4@583.14,-533.29 596.84,-518.07 v1(595.96,-501.39)
  Mid-Layer 1 w3.94: v2(-700.04,-569.26) -689.84,-644.68 -648.62,-685.04 v1(440.94,-685.04)
  Mid-Layer 2 w7.87: v1(440.94,-685.04) 509.84,-685.04 595.96,-598.92 v1(595.96,-501.39)
NXH_nRESET: U2.A6 U3.C5 | length 1602.5
  Mid-Layer 1 w3.94: v2(-682.75,-504.72) -638.43,-516.6 -601.24,-516.6 -438.63,-353.98 602.17,-353.98 640.1,-388.13 646.79,-394.82 646.79,-538.47 624.62,-560.64 v3(611.46,-560.64)
NXH_REFCLK: U2.B5 U3.E1 | length 1499.5
  Top w7.87: U3.E1@-721.55,-563.5 -732,-576 v1(-702.56,-661.42)
  Mid-Layer 1 w3.94: v1(-702.56,-661.42) -662.2,-701.77 497.05,-701.77 583.62,-615.2 v3(583.62,-561.13)
NXH_RX: U2.F4 U3.F4 | length 1270.7
  Top w3.94: v1(505.91,-647.64) 505.91,-612.95 U2.F4@514.76,-604.09
  Mid-Layer 1 w3.94: v2(-672.76,-553.51) -628.65,-619.09 v1(-602.36,-636.81)
  Mid-Layer 2 w7.87: v1(-602.36,-636.81) -591.54,-647.64 v1(505.91,-647.64)
NXH_TX: U2.E4 U3.F5 | length 1270.9
  Mid-Layer 1 w3.94: v2@-658.76,-545.28 v1(-617.13,-545.28) ; v1(337.9,-581.69) 466.54,-581.69 486.2,-601.35 518.15,-601.35 v3(528.44,-589.93)
  Mid-Layer 2 w7.87: v1(-617.13,-545.28) -603.28,-545.28 -535.36,-477.36 210.63,-477.36 232.66,-477.36 v1@336.99,-581.69
  other v2: -659.13,-545.64
NXH_UPDATE: U2.C5 U3.H2 | length 1355.6
  Top w3.94: U3.H2@-684.29,-596.54 v1@-672.97,-631.14
  Mid-Layer 1 w3.94: v1(-672.24,-630.91) -633.86,-669.29 513.78,-669.29 569.95,-613.12 v3(569.95,-575.29)
SCL: R2.1 U1.9 U2.D6 U3.H5 | length 2038.8
  Top w3.94: U3.H5@-643.38,-572.91 v1@-626,-590.29 ; U2.D6@570.43,-603.12 625.54,-603.12 637.8,-590.87 699.09,-527.4 U1.9@720.76,-504.96
  Top w7.87: v1(651.23,-227.11) R2.1@671.64,-246.82
  Mid-Layer 1 w3.94: v1(-626,-591.54) -560.06,-525.59 -498.87,-525.59 -411,-437.72 v1(-411,-419.41) ; v1(651.23,-227.11) 710.22,-280.22 710.22,-516.04 v1(698.98,-527.29)
  Mid-Layer 2 w7.87: v1(-411,-419.41) -411,-378.52 -404.53,-372.05 -312.01,-279.53 466.95,-279.53 519.37,-227.11 v1(651.23,-227.11)
SDA: R3.1 U1.8 U2.C6 U3.G5 U3.H6 | length 1938.4
  Top w3.94: U3.G5@-651.25,-559.28 U3.H6@-629.74,-565.04 v1(-575.79,-590.55) ; U2.C6@584.11,-588.96 611.37,-588.96 618.63,-581.69 v1(667.92,-530.66) 705.93,-491.29 U1.8@706.6,-491.28
  Top w7.87: v1(618.53,-261.35) R3.1@638.94,-281.06
  Mid-Layer 1 w3.94: v1(-575.79,-590.55) -559.06,-573.82 -502.82,-573.82 -388,-459 v1(-388,-398) ; v1(618.53,-261.35) 675.45,-312.6 675.45,-522.32 667.92,-529.86 v1(667.92,-530.66)
  Mid-Layer 2 w7.87: v1(-388,-398) -299.06,-309.06 -282.48,-309.06 475.39,-309.06 523.1,-261.35 v1(618.53,-261.35)
VCC: BT1.1 C1.2 C17.2 C19.2 U1.3 U4.3 U4.4 U5.3 U5.4 | length 2071.3
  Top w3.94: C17.2@-581.88,-385.7 C17.2@-580.83,-384.65
  Top w7.87: v1@-617.13,-209.66 -617.13,-375.87 -607.3,-385.7 C17.2@-581.88,-385.7 C19.2@-581.88,-430.7 U5.3@-581.88,-471.61 ; U5.4@-582.41,-500.09 -590.91,-500.09 -595,-496 -595,-476 -591.13,-472.13 U5.3@-582.41,-472.13 ; C17.2@-580.83,-384.65 -580.83,-363 -559.28,-363 -552.87,-356.59 U4.4@-552.87,-345.84 ; -580.83,-361 U4.3@-580.83,-345.84 ; v1(648.66,-365.6) 667.13,-383.43 667.23,-383.53 675.78,-381.05 713.69,-380.46 U1.3@732.83,-398.94
  Top w15.75: v1@-617.13,-209.66 -579,-171.54 BT1.1@-579,-2.23
  Mid-Layer 1 w7.87: v1(-617.13,-209.65) -512.65,-209.65 -428.01,-294.29 573.4,-294.29 608.98,-329.87 v1(648.66,-365.6)
VOUT: C2.2 D1.1 D2.1 D3.1 D4.1 D5.1 D6.1 U1.22 | length 3998.7
  Top w7.87: D4.1@-964.57,264.76 ccw(c25.24,-0.45) v1@-954.12,-301.98 ; U1.22@824.69,-397.34 846.47,-374.78 C2.2@884.66,-374.12 ; C2.2@884.6,-371.16 946.24,-309.51 v1(954.12,-301.98) ccw(c-25.24,-0.45) D3.1@964.57,264.76
  Mid-Layer 2 w7.87: -987.37,-356.81 ccw(c0,0) 954.51,-437.19 v1(954.12,-301.98) ; -987.13,-356.73 v1(-953.74,-302.17)
pads on no net: D1.0 D2.0 D3.0 D4.0 D5.0 D6.0 J1.0 J1.6 J1.7 J1.8 U1.11 U1.12 U1.13 U2.A1 U2.A2 U2.B1 U2.B2 U2.B3 U2.C1 U2.C2 U2.D1 U2.D2 U2.E2 U2.E3 U3.A3 U3.A4 U3.B4 U3.C3 U3.C4 U3.D1 U3.D2 U3.D3 U3.D4 U3.E2 U3.E3 U3.E6 U3.F1 U3.F6 U3.G1 U3.G2 U3.G3 U3.G4 U3.G6 U3.H1 U3.H3 U3.H4 W1.0 W2.0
